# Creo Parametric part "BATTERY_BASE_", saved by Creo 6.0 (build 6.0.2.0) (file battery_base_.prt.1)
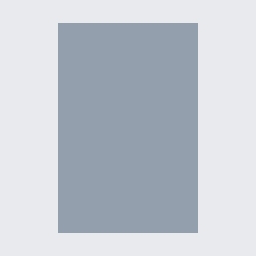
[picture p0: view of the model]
Units: Inch lbm Second (Pro/E Default); INCH, POUND, SECS

Created from: INLBS_PART_SOLID.PRT

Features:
  1. datum plane "RIGHT"
  2. datum plane "TOP"
  3. datum plane "FRONT"
  4. coordinate system
  5. sketch "Sketch 1"
  6. extrusion "Extrude 1"

Surfaces: 6 plane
